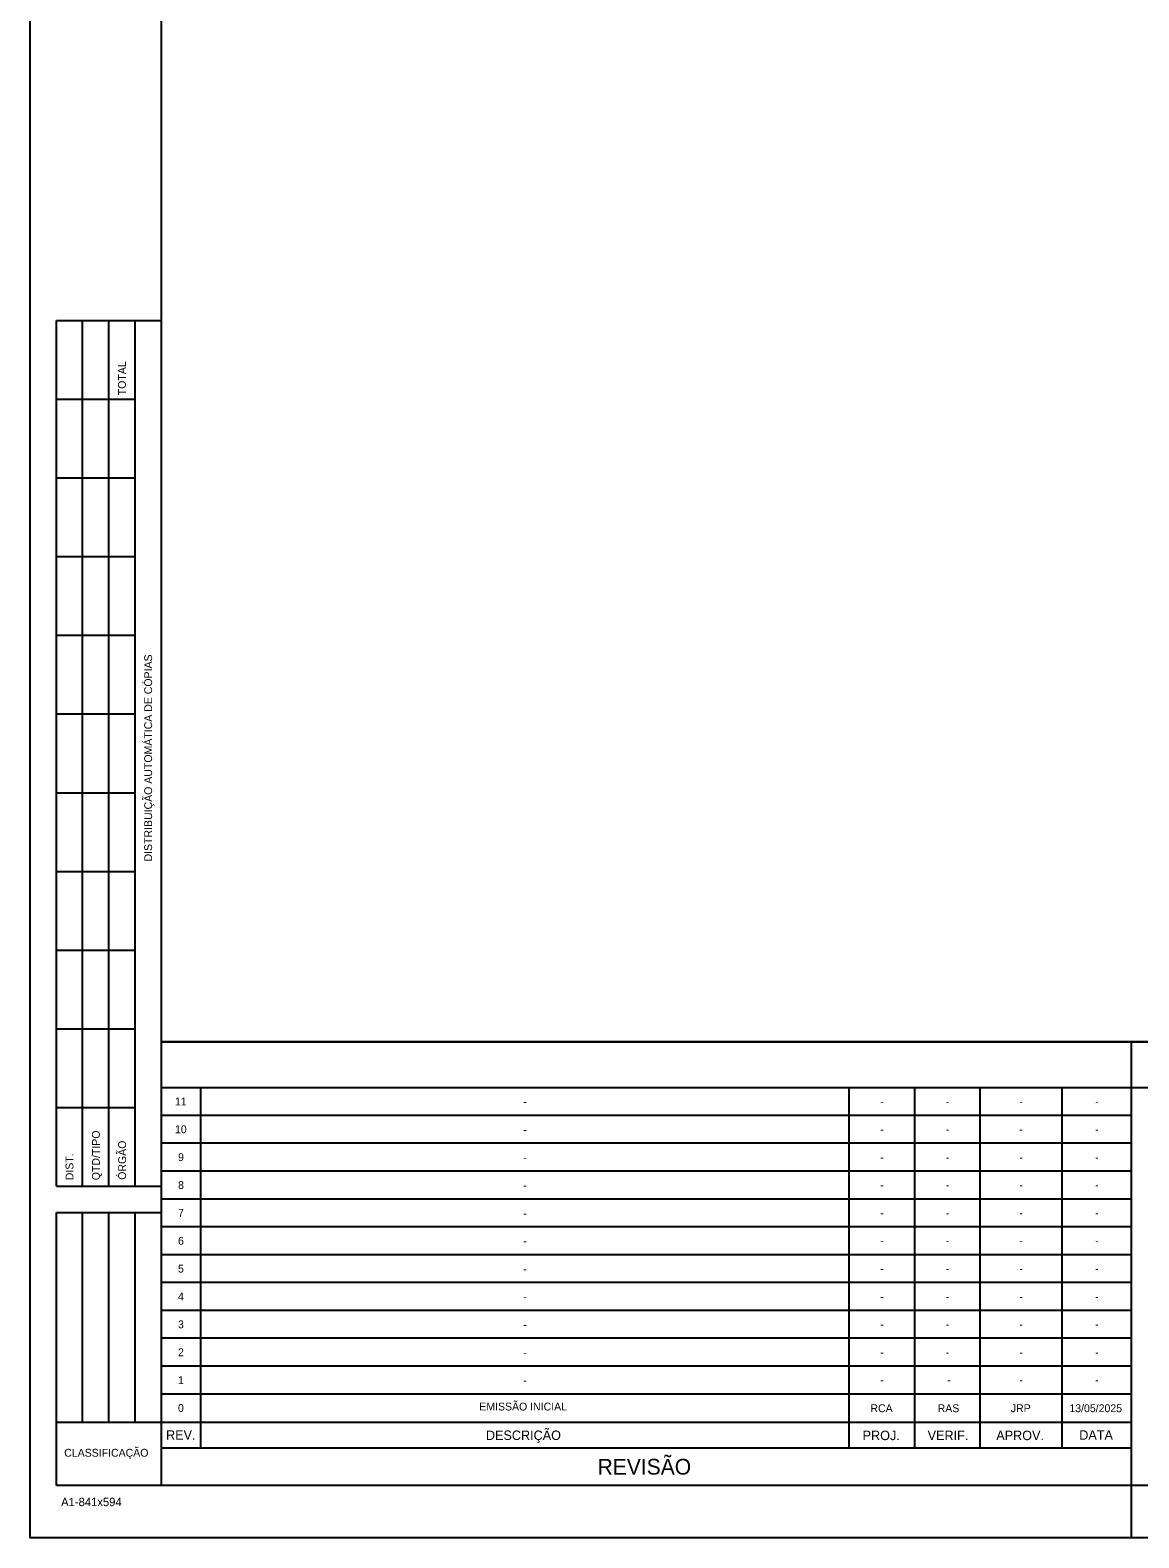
# Model space of a CAD drawing. Extents: x 0 to 841, y 0 to 594.
# Drawn here: x 0 to 211.4, y 0 to 287.3 of the extents above; entities that cross this region are included whole.
import ezdxf

# ---------------------------------------------------------------- set-up
doc = ezdxf.new("R2010")
doc.units = 0
for name, color, linetype in [('FORMATO', 7, 'Continuous'), ('MEIO_FIO_GUIA', 7, 'Continuous'), ('TEXTO', 7, 'Continuous')]:
    doc.layers.add(name, color=color, linetype=linetype)

msp = doc.modelspace()

# ---------------------------------------------------------------- linework, layer by layer
at = {"layer": 'FORMATO'}
for p, q in [((5, 67), (5, 232)), ((5, 232), (25, 232)), ((10, 67), (10, 232)), ((15, 67), (15, 232)), ((20, 67), (20, 232)), ((5, 217), (20, 217)), ((5, 202), (20, 202)), ((5, 187), (20, 187)), ((5, 172), (20, 172)), ((5, 157), (20, 157)), ((5, 142), (20, 142)), ((5, 127), (20, 127)), ((5, 112), (20, 112)), ((5, 97), (20, 97)), ((831.01, 94.54), (25, 94.54)), ((210, 10), (210, 94.54)), ((25, 85.81), (656, 85.81)), ((32.55, 17.09), (32.55, 85.81)), ((156.17, 17.09), (156.17, 85.81)), ((168.66, 17.09), (168.66, 85.81)), ((181.15, 17.09), (181.15, 85.81)), ((196.74, 17.09), (196.74, 85.81)), ((5, 82), (20, 82)), ((210, 80.5), (25, 80.5)), ((210, 75.19), (25, 75.19)), ((210, 69.88), (25, 69.88)), ((5, 67), (25, 67)), ((210, 64.57), (25, 64.57)), ((5, 10), (5, 62)), ((5, 62), (25, 62)), ((10, 22), (10, 62)), ((15, 22), (15, 62)), ((20, 22), (20, 62)), ((210, 59.26), (25, 59.26)), ((210, 53.95), (25, 53.95)), ((210, 48.64), (25, 48.64)), ((210, 43.33), (25, 43.34)), ((210, 38.02), (25, 38.03)), ((210, 32.71), (25, 32.72)), ((210, 27.4), (25, 27.41)), ((25, 22), (5, 22)), ((210, 22), (25, 22)), ((210, 17.09), (25, 17.09)), ((831.01, 10), (5, 10)), ((210, 0), (210, 10))]:
    msp.add_line(p, q, dxfattribs=at)
msp.add_lwpolyline([(0, 594), (841, 594), (841, 0), (0, 0)], close=True, dxfattribs=at)
msp.add_lwpolyline([(831.01, 10), (831.01, 584), (25, 584), (25, 10)], dxfattribs=at)
at = {"layer": 'MEIO_FIO_GUIA'}
msp.add_lwpolyline([(25, 584), (25, 94.54), (572.92, 94.54), (831.01, 94.54), (831.01, 251.27), (831.01, 584)], close=True, dxfattribs=at)

# ---------------------------------------------------------------- texts
at = {"layer": 'FORMATO'}
for s, height, rotation, p in [('TOTAL', 1.5, 90, (18.25, 217.74)), ('DISTRIBUIÇÃO AUTOMÁTICA DE CÓPIAS', 1.5, 90, (23.25, 128.89)), ('QTD/TIPO', 1.5, 90, (13.29, 68.15)), ('ÓRGÃO', 1.5, 90, (18.29, 68.23)), ('DIST.', 1.5, 90, (8.25, 68.15)), ('REV.', 1.8, 360, (25.91, 18.7)), ('DESCRIÇÃO', 1.8, 360, (86.89, 18.65)), ('PROJ.', 1.8, 360, (158.71, 18.62)), ('VERIF.', 1.8, 360, (171.11, 18.62)), ('APROV.', 1.8, 360, (184.19, 18.62)), ('DATA', 1.8, 360, (200.01, 18.69)), ('CLASSIFICAÇÃO', 1.5, 360, (6.5, 15.46)), ('REVISÃO', 3, 360, (108.18, 12.05))]:
    msp.add_text(s, height=height, rotation=rotation, dxfattribs=at).set_placement(p)
msp.add_text('A1-841x594', height=1.6, dxfattribs=at).set_placement((5.91, 6.04))
at = {"layer": 'TEXTO'}
for s, p in [('11', (27.61, 82.41)), ('-', (94.01, 82.36)), ('-', (162.07, 82.41)), ('-', (174.56, 82.41)), ('-', (188.6, 82.41)), ('-', (203.02, 82.41)), ('10', (27.61, 77.1)), ('-', (94.01, 77.05)), ('-', (162.06, 77.1)), ('-', (174.55, 77.1)), ('-', (188.59, 77.1)), ('-', (203.02, 77.1)), ('9', (28.2, 71.79)), ('-', (94.01, 71.74)), ('-', (162.07, 71.79)), ('-', (174.56, 71.79)), ('-', (188.6, 71.79)), ('-', (203.02, 71.79)), ('8', (28.2, 66.48)), ('-', (94.01, 66.43)), ('-', (162.07, 66.48)), ('-', (174.56, 66.48)), ('-', (188.6, 66.48)), ('-', (203.02, 66.48)), ('7', (28.2, 61.17)), ('-', (94.01, 61.12)), ('-', (162.07, 61.17)), ('-', (174.56, 61.17)), ('-', (188.6, 61.17)), ('-', (203.02, 61.17)), ('6', (28.19, 55.86)), ('-', (94.01, 55.81)), ('-', (162.06, 55.86)), ('-', (174.55, 55.86)), ('-', (188.59, 55.86)), ('-', (203.02, 55.86)), ('5', (28.19, 50.55)), ('-', (94.01, 50.5)), ('-', (162.07, 50.55)), ('-', (174.56, 50.55)), ('-', (188.6, 50.55)), ('-', (203.02, 50.55)), ('4', (28.19, 45.24)), ('-', (94.01, 45.19)), ('-', (162.07, 45.24)), ('-', (174.56, 45.24)), ('-', (188.6, 45.24)), ('-', (203.02, 45.24)), ('3', (28.19, 39.93)), ('-', (94.01, 39.88)), ('-', (162.07, 39.93)), ('-', (174.56, 39.93)), ('-', (188.6, 39.93)), ('-', (203.02, 39.93)), ('2', (28.19, 34.62)), ('-', (94.01, 34.58)), ('-', (162.07, 34.62)), ('-', (174.56, 34.62)), ('-', (188.6, 34.62)), ('-', (203.02, 34.62)), ('1', (28.19, 29.31)), ('-', (94.01, 29.27)), ('-', (162.07, 29.35)), ('-', (174.83, 29.35)), ('-', (188.6, 29.35)), ('-', (203.02, 29.35)), ('EMISSÃO INICIAL', (85.63, 24.27)), ('0', (28.19, 24)), ('RCA', (160.2, 23.95)), ('RAS', (173.02, 23.95)), ('JRP', (186.96, 23.95)), ('13/05/2025', (198.13, 23.95))]:
    msp.add_text(s, height=1.5, rotation=359.9989, dxfattribs=at).set_placement(p)

doc.saveas('drawing.dxf')
